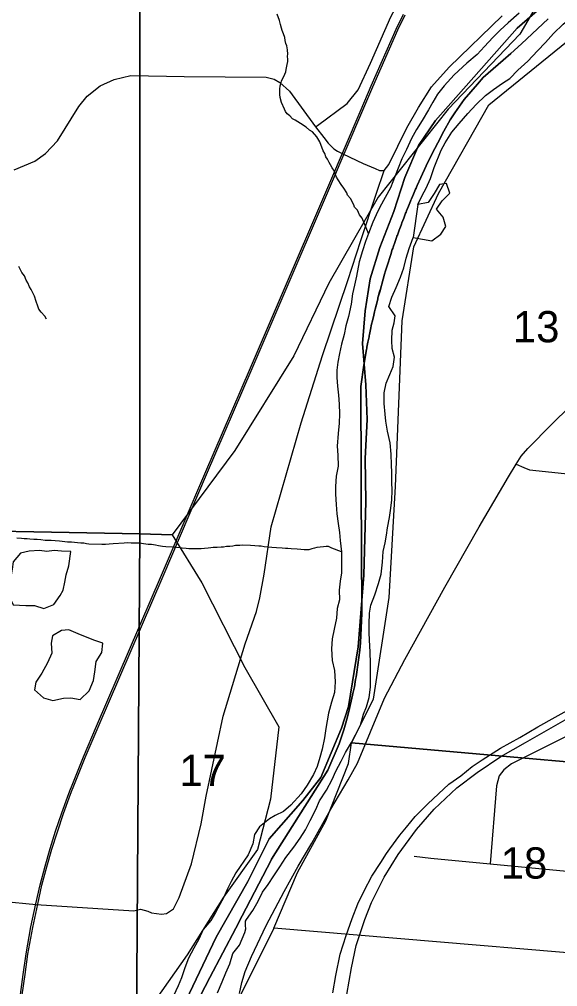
# Model space of a CAD drawing. Extents: x 0 to 34, y 0 to 22.
# Drawn here: x 3.85 to 4.57, y 14.854 to 16.149 of the extents above; entities that cross this region are included whole.
import ezdxf

# ---------------------------------------------------------------- set-up
doc = ezdxf.new("R2010")
doc.units = 0
for name, color, linetype in [('Default', 7, 'Continuous'), ('GM_X_City_Street', 7, 'Continuous'), ('GM_X_Interstate_Route', 7, 'Continuous'), ('GM_X_Major_River', 7, 'Continuous'), ('GM_X_Minor_Lake', 7, 'Continuous'), ('GM_X_Minor_River', 7, 'Continuous'), ('GM_X_Rail_Line', 7, 'Continuous'), ('GM_X_Section', 7, 'Continuous'), ('GM_X_Section_Text', 7, 'Continuous'), ('GM_X_State_Route', 7, 'Continuous'), ('GM_X_Township_Road', 7, 'Continuous'), ('SC_Shading3', 7, 'Continuous')]:
    doc.layers.add(name, color=color, linetype=linetype)

msp = doc.modelspace()

# ---------------------------------------------------------------- linework, layer by layer
at = {"layer": 'Default'}
msp.add_lwpolyline([(3.9705, 14.1), (4.7349, 14.1), (4.7957, 14.8813), (4.1906, 14.9321), (4.0525, 14.6548), (3.9958, 14.4577), (3.9463, 14.3814), (3.9481, 14.3196)], close=True, dxfattribs=at)
at = {"layer": 'GM_X_City_Street'}
for points in [[(4.2465, 16.0051), (4.249, 16.0069), (4.2886, 16.0363), (4.3032, 16.0547), (4.3197, 16.0901), (4.3471, 16.1524), (4.3736, 16.2015), (4.3929, 16.2355), (4.4288, 16.2927), (4.511, 16.4027), (4.5218, 16.4197), (4.5289, 16.4358), (4.5336, 16.4532), (4.5369, 16.4661)], [(4.5149, 15.5535), (4.5216, 15.5642), (4.5305, 15.5745), (4.5624, 15.6068), (4.7794, 15.82), (4.87, 15.9094), (4.8959, 15.9365), (4.9216, 15.9589), (4.9372, 15.9717), (4.9543, 15.9837), (5.0154, 16.0193), (5.0715, 16.0516), (5.1047, 16.0699), (5.1468, 16.091), (5.1632, 16.1008), (5.1685, 16.1061), (5.1775, 16.1154), (5.1852, 16.1256), (5.1933, 16.1399), (5.2233, 16.1956), (5.23, 16.2068), (5.2368, 16.2142), (5.2425, 16.2183)], [(4.0468, 14.9519), (4.0562, 14.9583), (4.0638, 14.9733), (4.0804, 15.0185), (4.0934, 15.0718), (4.0998, 15.1089), (4.1229, 15.216), (4.152, 15.3128), (4.1673, 15.3563), (4.1718, 15.3744), (4.1774, 15.4062), (4.1868, 15.4697), (4.2269, 15.6089), (4.2558, 15.6988), (4.2897, 15.7992), (4.3069, 15.853), (4.328, 15.9162), (4.3382, 15.9467), (4.3445, 15.9547), (4.3686, 16.0037), (4.3841, 16.0311), (4.4017, 16.0587), (4.4251, 16.0847), (4.4959, 16.1536)], [(3.8433, 15.9474), (3.8706, 15.9593), (3.8851, 15.9695), (3.9013, 15.9863), (3.9297, 16.0321), (3.9408, 16.0459), (3.9582, 16.0599), (3.9771, 16.0684), (3.9991, 16.0736), (4.0704, 16.0722), (4.1804, 16.0717), (4.1908, 16.0689), (4.1984, 16.0646), (4.2114, 16.0528), (4.2465, 16.0051)], [(4.2465, 16.0051), (4.2575, 15.9906), (4.2634, 15.9833), (4.2669, 15.9794), (4.271, 15.9756), (4.2758, 15.9726), (4.2827, 15.9688), (4.3101, 15.9561), (4.326, 15.9493), (4.3319, 15.9467), (4.3382, 15.9467)], [(4.1444, 14.8447), (4.1476, 14.8597), (4.1521, 14.8745), (4.1606, 14.8942), (4.1805, 14.9357), (4.2043, 14.9815), (4.2229, 15.0151), (4.2416, 15.0463), (4.2668, 15.0918), (4.2902, 15.131), (4.3023, 15.1533), (4.3198, 15.1951), (4.3386, 15.24), (4.3658, 15.2918), (4.4194, 15.389), (4.4653, 15.4696), (4.5044, 15.5366), (4.5149, 15.5535)], [(4.5149, 15.5535), (4.525, 15.5488), (4.5328, 15.5458), (4.6135, 15.5372), (4.839, 15.5157), (4.85, 15.5147)], [(4.7473, 15.1764), (4.6964, 15.1876), (4.612, 15.1957), (4.6004, 15.1961), (4.5936, 15.195), (4.5869, 15.1914), (4.5085, 15.1522), (4.4981, 15.1441), (4.4919, 15.1361), (4.4886, 15.1229), (4.4801, 15.0184)], [(4.3785, 15.0286), (4.4007, 15.026), (4.4801, 15.0184), (4.6944, 14.9979), (4.7286, 14.9924), (4.8064, 14.9848)], [(3.78, 14.9731), (3.8726, 14.9642), (4.0031, 14.9555), (4.0122, 14.9578), (4.0218, 14.9551), (4.0268, 14.9528), (4.0404, 14.951), (4.0468, 14.9519)]]:
    msp.add_lwpolyline(points, dxfattribs=at)
at = {"layer": 'GM_X_Interstate_Route'}
for points in [[(4.3958, 15.0979), (4.3965, 15.0986), (4.411, 15.1122), (4.4246, 15.1249), (4.4406, 15.1364), (4.4557, 15.1489), (4.4695, 15.1575), (4.4939, 15.1734), (4.5199, 15.1877), (4.544, 15.2017), (4.5943, 15.2301), (4.6364, 15.2539), (4.7317, 15.3079), (4.7824, 15.3368), (4.7921, 15.343)], [(4.3383, 15.0004), (4.3568, 15.0308), (4.3814, 15.0645), (4.4051, 15.0915), (4.4356, 15.12), (4.4626, 15.1408), (4.4941, 15.1619), (4.5273, 15.181), (4.5992, 15.222), (4.6413, 15.2458), (4.7367, 15.2999), (4.7823, 15.3258)], [(4.2695, 14.8457), (4.2734, 14.8691), (4.2795, 14.8977), (4.2873, 14.9227), (4.2953, 14.9451), (4.303, 14.9647), (4.3113, 14.9821), (4.3218, 15.0018), (4.3335, 15.0201), (4.3414, 15.0322), (4.3457, 15.0387), (4.3591, 15.057), (4.3679, 15.0673), (4.3797, 15.0816), (4.3958, 15.0979)], [(4.2876, 14.8397), (4.288, 14.8437), (4.2943, 14.8792), (4.3009, 14.909), (4.3123, 14.9437), (4.3213, 14.9665), (4.3362, 14.997), (4.3383, 15.0004)]]:
    msp.add_lwpolyline(points, dxfattribs=at)
at = {"layer": 'GM_X_Major_River'}
msp.add_line((4.3831, 15.9009), (4.3769, 15.8569), dxfattribs=at)
for points in [[(4.5186, 16.1571), (4.5039, 16.1441), (4.4935, 16.1344), (4.4834, 16.1248), (4.4726, 16.1124), (4.4625, 16.102), (4.449, 16.0901), (4.432, 16.0748), (4.4184, 16.0599), (4.4095, 16.0486), (4.4032, 16.0381), (4.3973, 16.0279), (4.3891, 16.0137), (4.3816, 16.0016), (4.3749, 15.9892), (4.3682, 15.9745), (4.3619, 15.9621), (4.3571, 15.9496), (4.3531, 15.9395), (4.3467, 15.9236), (4.3396, 15.9104), (4.3322, 15.8977), (4.3274, 15.8871), (4.3231, 15.8773), (4.3171, 15.8622), (4.3131, 15.8516), (4.3094, 15.8392), (4.3046, 15.8241), (4.3012, 15.8051), (4.2986, 15.793), (4.2958, 15.7816), (4.294, 15.7676), (4.2903, 15.7513), (4.287, 15.7385), (4.2848, 15.7271), (4.2812, 15.7139), (4.2783, 15.7018), (4.2762, 15.69), (4.2748, 15.6794), (4.275, 15.6695), (4.2759, 15.6577), (4.2772, 15.6459), (4.2781, 15.6337), (4.2782, 15.6208), (4.278, 15.6082), (4.2766, 15.5946), (4.2755, 15.5775), (4.2764, 15.5653)], [(4.3831, 15.9009), (4.389, 15.9129), (4.3945, 15.9231), (4.4001, 15.9359), (4.4049, 15.9506), (4.4145, 15.974), (4.42, 15.9838), (4.4286, 15.9981), (4.4387, 16.0097), (4.4503, 16.0231), (4.4612, 16.0351), (4.4739, 16.047), (4.4843, 16.0548), (4.4966, 16.0633), (4.5063, 16.0699), (4.5171, 16.0811), (4.5302, 16.093), (4.5434, 16.1069), (4.5542, 16.1181), (4.5647, 16.13), (4.5779, 16.1427), (4.5929, 16.1553)], [(4.3769, 15.8569), (4.4019, 15.8526), (4.4138, 15.8615), (4.4208, 15.8716), (4.4169, 15.8842), (4.408, 15.8947), (4.4158, 15.9059), (4.4262, 15.9164), (4.4216, 15.9294), (4.4121, 15.928), (4.405, 15.9156), (4.3972, 15.9036), (4.3831, 15.9009)], [(4.1152, 14.8456), (4.1215, 14.8606), (4.1263, 14.8723), (4.1315, 14.8844), (4.1359, 14.8984), (4.1445, 14.9096), (4.1517, 14.9266), (4.1529, 14.9315), (4.1526, 14.9357), (4.1527, 14.9414), (4.1527, 14.9418), (4.1539, 14.9441), (4.1625, 14.9561), (4.1695, 14.9685), (4.1755, 14.9805), (4.1829, 14.9907), (4.1907, 15.0023), (4.1985, 15.0143), (4.2067, 15.0267), (4.2172, 15.0406), (4.2258, 15.0526), (4.2329, 15.0638), (4.2392, 15.0766), (4.2467, 15.0913), (4.2518, 15.1026), (4.2608, 15.1169), (4.2687, 15.1312), (4.2735, 15.1425), (4.2805, 15.1557), (4.2865, 15.1674), (4.2943, 15.1809), (4.2998, 15.1911), (4.3065, 15.2042), (4.3106, 15.2186), (4.3146, 15.2284), (4.3183, 15.2409), (4.32, 15.2549), (4.32, 15.2713), (4.3199, 15.2865), (4.3194, 15.3021), (4.3186, 15.3177), (4.318, 15.328), (4.3179, 15.3394), (4.3186, 15.3538), (4.3203, 15.3648), (4.3259, 15.3784), (4.3307, 15.3939), (4.334, 15.406), (4.3358, 15.4223), (4.3369, 15.4364), (4.3394, 15.4481), (4.3411, 15.4583), (4.3428, 15.4682), (4.3453, 15.4822), (4.3471, 15.4947), (4.3484, 15.5057), (4.3491, 15.5183), (4.3485, 15.5293), (4.3484, 15.5422), (4.3482, 15.5525), (4.3477, 15.567), (4.3461, 15.5818), (4.3427, 15.5978), (4.3402, 15.6108), (4.3397, 15.6203), (4.3381, 15.6348), (4.3383, 15.6489), (4.3409, 15.6618), (4.3456, 15.6735), (4.35, 15.6844), (4.3518, 15.6969), (4.349, 15.7084), (4.3484, 15.719), (4.3491, 15.7327), (4.3515, 15.7425), (4.3529, 15.752), (4.3444, 15.7644), (4.3484, 15.7772), (4.3544, 15.79), (4.3599, 15.804), (4.3644, 15.8161), (4.3676, 15.8293), (4.3717, 15.8421), (4.3769, 15.8569)], [(4.2764, 15.5653), (4.2765, 15.5508), (4.2739, 15.5376), (4.2729, 15.5235), (4.2731, 15.5133), (4.274, 15.4996), (4.2749, 15.487), (4.2765, 15.474), (4.2785, 15.4618), (4.2795, 15.4512), (4.2811, 15.4359), (4.2812, 15.4215), (4.2809, 15.4082), (4.2792, 15.3968), (4.2778, 15.385), (4.2783, 15.3717), (4.2754, 15.3604), (4.2744, 15.3471), (4.2711, 15.3327), (4.2686, 15.3198), (4.2679, 15.3061), (4.2688, 15.2905), (4.2715, 15.2772), (4.2728, 15.2619), (4.2717, 15.2479), (4.2677, 15.2347), (4.2636, 15.2203), (4.2602, 15.1994), (4.2584, 15.1873), (4.2551, 15.1718), (4.2522, 15.1608), (4.2485, 15.1487), (4.2438, 15.1378), (4.2352, 15.1239), (4.2273, 15.1122), (4.2134, 15.0969), (4.2037, 15.0887), (4.1923, 15.0831)], [(4.1923, 15.0831), (4.1846, 15.0788), (4.1715, 15.0681), (4.1648, 15.0579), (4.1623, 15.0451), (4.1563, 15.0303), (4.1399, 15.0063), (4.1336, 14.9947), (4.1281, 14.9841), (4.1237, 14.9739), (4.1182, 14.9638), (4.1123, 14.9532), (4.1061, 14.9427), (4.096, 14.9304), (4.09, 14.9175), (4.0837, 14.9055), (4.0762, 14.8923), (4.0714, 14.8791), (4.067, 14.8659), (4.0626, 14.8549), (4.0563, 14.8418)]]:
    msp.add_lwpolyline(points, dxfattribs=at)
at = {"layer": 'GM_X_Minor_Lake'}
for points in [[(3.9188, 15.4365), (3.9063, 15.4371), (3.8964, 15.4377), (3.8869, 15.4367), (3.8771, 15.4377), (3.863, 15.4368), (3.8516, 15.4344), (3.8419, 15.4228), (3.8402, 15.4129), (3.8388, 15.4027), (3.8375, 15.3909), (3.8364, 15.3769), (3.8419, 15.365), (3.8586, 15.3643), (3.8703, 15.3641), (3.8828, 15.3604), (3.8961, 15.3655), (3.9047, 15.3778)], [(3.9047, 15.3778), (3.9087, 15.385), (3.9108, 15.3956), (3.9129, 15.4054), (3.9161, 15.4172), (3.9188, 15.4365)], [(3.9288, 15.3264), (3.9164, 15.3316), (3.9065, 15.331), (3.8942, 15.3237), (3.8925, 15.3138), (3.8934, 15.3005), (3.8878, 15.2877), (3.8803, 15.2737), (3.8721, 15.2614), (3.8704, 15.2515), (3.8823, 15.2406), (3.8948, 15.2373), (3.9093, 15.2401), (3.9188, 15.2407), (3.9312, 15.2382), (3.9436, 15.2501), (3.9492, 15.2637)], [(3.9492, 15.2637), (3.9509, 15.2754), (3.9527, 15.2894), (3.9605, 15.3015), (3.9619, 15.314), (3.9495, 15.3177), (3.9288, 15.3264)]]:
    msp.add_lwpolyline(points, dxfattribs=at)
at = {"layer": 'GM_X_Minor_River'}
for points in [[(4.3171, 15.8622), (4.3086, 15.8826), (4.3053, 15.8873), (4.3024, 15.8934), (4.2987, 15.8977), (4.2977, 15.9008), (4.2933, 15.9089), (4.2892, 15.9135), (4.2882, 15.9166), (4.2841, 15.9228), (4.2808, 15.9278), (4.2768, 15.934), (4.2746, 15.9378), (4.2724, 15.9421), (4.2718, 15.9459), (4.2685, 15.9502), (4.2663, 15.954), (4.2645, 15.9571), (4.2623, 15.9617), (4.2601, 15.9648), (4.2587, 15.9694), (4.2565, 15.9729), (4.2522, 15.9851), (4.2482, 15.9917), (4.2423, 15.9983), (4.2381, 16.0007), (4.2337, 16.0046), (4.2262, 16.0094), (4.2191, 16.0141), (4.2153, 16.0157), (4.212, 16.0196), (4.2083, 16.0223), (4.206, 16.0254), (4.2046, 16.0285), (4.2006, 16.0374), (4.1989, 16.0442), (4.1986, 16.0484), (4.1987, 16.0515), (4.1984, 16.0553), (4.1989, 16.0598), (4.1997, 16.0628), (4.201, 16.0662), (4.2022, 16.0692), (4.2038, 16.0726), (4.2054, 16.0756), (4.2066, 16.0786), (4.207, 16.0817), (4.2084, 16.0885), (4.2092, 16.0923), (4.2093, 16.0953), (4.209, 16.0995), (4.2091, 16.1025), (4.2088, 16.1082), (4.2078, 16.1136), (4.2068, 16.1166), (4.2057, 16.1208), (4.2051, 16.1247), (4.2037, 16.1296), (4.2019, 16.1342), (4.2008, 16.1373), (4.1994, 16.1419), (4.198, 16.1473), (4.1948, 16.1557)], [(3.8862, 15.7475), (3.884, 15.7517), (3.8792, 15.7568), (3.8763, 15.7611), (3.8749, 15.7649), (3.8724, 15.771), (3.8703, 15.7783), (3.8684, 15.7818), (3.8659, 15.7875), (3.8637, 15.791), (3.8616, 15.7964), (3.859, 15.7999), (3.8568, 15.8056), (3.8535, 15.8099), (3.8495, 15.818)], [(4.2811, 15.4359), (4.2681, 15.4408), (4.2636, 15.4432), (4.2606, 15.4433), (4.2571, 15.443), (4.2525, 15.4423), (4.2483, 15.4417), (4.2449, 15.441), (4.2415, 15.44), (4.2373, 15.4389), (4.2342, 15.4386), (4.2312, 15.4387), (4.2266, 15.4392), (4.2217, 15.4397), (4.2137, 15.4403), (4.2091, 15.4404), (4.2061, 15.4405), (4.2019, 15.4409), (4.194, 15.4415), (4.1879, 15.442), (4.1822, 15.4422), (4.1776, 15.4427), (4.1735, 15.4435), (4.1704, 15.4436), (4.1651, 15.4441), (4.1594, 15.4446), (4.1484, 15.4449), (4.145, 15.4446), (4.1393, 15.4444), (4.1355, 15.4437), (4.1316, 15.4434), (4.1274, 15.4432), (4.1233, 15.4425), (4.1202, 15.4422), (4.1149, 15.442), (4.1092, 15.4417), (4.1061, 15.4414), (4.1027, 15.4411), (4.0977, 15.4405), (4.0932, 15.4402), (4.089, 15.4403), (4.084, 15.4401), (4.0802, 15.4401), (4.0768, 15.4402), (4.0734, 15.4407), (4.0681, 15.4408), (4.0647, 15.4413), (4.0601, 15.4418), (4.0548, 15.4423), (4.0461, 15.4429), (4.0415, 15.4434), (4.0362, 15.4443), (4.0324, 15.4448), (4.0267, 15.4457), (4.0222, 15.4461), (4.0161, 15.4467), (4.0108, 15.4476), (4.0051, 15.4477), (3.9998, 15.4478), (3.9948, 15.448), (3.9903, 15.4477), (3.9754, 15.4469), (3.9701, 15.4463), (3.9651, 15.446), (3.9606, 15.4458), (3.9431, 15.4462), (3.94, 15.4467), (3.9363, 15.4475), (3.9321, 15.4476), (3.9279, 15.4481), (3.92, 15.4491), (3.9143, 15.4492), (3.9074, 15.4501), (3.9036, 15.4502), (3.8979, 15.4507), (3.8926, 15.4512), (3.8846, 15.4514), (3.8786, 15.452), (3.874, 15.4525), (3.8695, 15.4526), (3.8641, 15.4531), (3.8607, 15.4536), (3.8566, 15.4537), (3.8531, 15.4541), (3.8467, 15.4543)]]:
    msp.add_lwpolyline(points, dxfattribs=at)
at = {"layer": 'GM_X_Rail_Line'}
for points in [[(3.8516, 14.8433), (3.8552, 14.8705), (3.859, 14.8978), (3.8656, 14.9339), (3.8722, 14.965), (3.8779, 14.9904), (3.8845, 15.0151), (3.8913, 15.0389), (3.8986, 15.0622), (3.907, 15.0867), (3.9145, 15.1077), (3.9175, 15.1162), (3.9206, 15.1239), (3.936, 15.1617), (3.9532, 15.2026), (4.0402, 15.4047), (4.0982, 15.5407), (4.1593, 15.6826), (4.1982, 15.7729), (4.2643, 15.927), (4.3073, 16.0284), (4.3208, 16.0598), (4.3543, 16.1358), (4.3639, 16.1559)], [(3.854, 14.843), (3.8577, 14.8702), (3.8615, 14.8974), (3.868, 14.9334), (3.8746, 14.9645), (3.8803, 14.9898), (3.8869, 15.0144), (3.8936, 15.0382), (3.9009, 15.0614), (3.9093, 15.0859), (3.9169, 15.1069), (3.9198, 15.1153), (3.9229, 15.123), (3.9383, 15.1608), (3.9555, 15.2016), (4.0425, 15.4037), (4.1004, 15.5397), (4.1616, 15.6816), (4.2005, 15.772), (4.2665, 15.926), (4.3096, 16.0275), (4.3231, 16.0588), (4.3565, 16.1348), (4.3662, 16.1548)]]:
    msp.add_lwpolyline(points, dxfattribs=at)
at = {"layer": 'GM_X_Section'}
for points in [[(3.0135, 16.4807), (4.0113, 16.4768), (4.0112, 15.46), (3.0168, 15.4789)], [(4.0113, 16.4768), (5.016, 16.4735), (5.0144, 16.4489), (4.9559, 16.4588), (4.9027, 16.4533), (4.8303, 16.4274), (4.767, 16.3854), (4.6663, 16.3267), (4.586, 16.2434), (4.5198, 16.1291), (4.4237, 16.0287), (4.3302, 15.9111), (4.264, 15.7957), (4.2171, 15.6985), (4.1382, 15.5716), (4.0543, 15.4588), (4.0112, 15.46)], [(4.6046, 16.1438), (4.9109, 16.1221), (4.8205, 15.1342), (4.2945, 15.1804), (4.324, 15.239), (4.3447, 15.3749), (4.3532, 15.5236), (4.3623, 15.7454), (4.3778, 15.8443), (4.4109, 15.9156), (4.4783, 16.0344), (4.5821, 16.1188)], [(3.0168, 15.4789), (4.0112, 15.46), (4.0068, 14.8003), (3.9922, 14.7706), (3.9618, 14.7034), (3.9313, 14.6142), (3.9035, 14.5261), (3.8947, 14.4604), (3.0051, 14.4664), (3.0163, 15.4353)], [(4.0112, 15.46), (4.0543, 15.4588), (4.0944, 15.3944), (4.1517, 15.2812), (4.1972, 15.202), (4.1863, 15.1048), (4.1688, 15.0374), (4.1233, 14.9738), (4.0748, 14.8967), (4.0068, 14.8003)], [(4.2945, 15.1804), (4.8205, 15.1342), (4.7957, 14.8813), (4.1906, 14.9321), (4.222, 15.0068), (4.26, 15.0762), (4.2906, 15.1529)]]:
    msp.add_lwpolyline(points, close=True, dxfattribs=at)
at = {"layer": 'GM_X_State_Route'}
msp.add_lwpolyline([(4.0435, 14.7476), (4.1051, 14.8662), (4.1395, 14.9324), (4.148, 14.9487), (4.1868, 15.0235), (4.1876, 15.0247), (4.2626, 15.1439), (4.2781, 15.179), (4.2812, 15.1884), (4.2841, 15.1979), (4.2869, 15.2074), (4.2895, 15.2169), (4.2919, 15.2265), (4.2942, 15.2361), (4.296, 15.2441), (4.2964, 15.2463), (4.2983, 15.2555), (4.2994, 15.262), (4.3, 15.2652), (4.3006, 15.2686), (4.3016, 15.275), (4.303, 15.2848), (4.3043, 15.2946), (4.3054, 15.3044), (4.3063, 15.3143), (4.307, 15.3241), (4.3076, 15.334), (4.308, 15.3439), (4.3082, 15.3538), (4.3082, 15.364), (4.3082, 15.378), (4.308, 15.4196), (4.3071, 15.6575), (4.3109, 15.686), (4.3146, 15.7068), (4.3149, 15.7088), (4.3152, 15.7101), (4.3165, 15.7169), (4.3179, 15.7238), (4.3182, 15.7254), (4.3185, 15.7271), (4.32, 15.7339), (4.3214, 15.7407), (4.3218, 15.7423), (4.3222, 15.744), (4.3238, 15.7508), (4.3253, 15.7576), (4.3257, 15.7592), (4.3261, 15.7608), (4.3278, 15.7676), (4.3295, 15.7744), (4.3299, 15.776), (4.3303, 15.7776), (4.3321, 15.7842), (4.3335, 15.7892), (4.334, 15.7911), (4.3344, 15.7926), (4.3349, 15.7942), (4.3368, 15.801), (4.3387, 15.8077), (4.3392, 15.8093), (4.3397, 15.8109), (4.3418, 15.8175), (4.3438, 15.8242), (4.3443, 15.8258), (4.3448, 15.8274), (4.347, 15.834), (4.3491, 15.8407), (4.3497, 15.8422), (4.3502, 15.8438), (4.3525, 15.8504), (4.3548, 15.857), (4.3553, 15.8586), (4.3559, 15.8601), (4.3583, 15.8667), (4.3607, 15.8733), (4.3613, 15.8748), (4.3618, 15.8764), (4.3644, 15.8829), (4.3669, 15.8894), (4.3675, 15.8909), (4.3681, 15.8925), (4.3707, 15.899), (4.3733, 15.9054), (4.374, 15.907), (4.3746, 15.9085), (4.3774, 15.9149), (4.3801, 15.9214), (4.3808, 15.9229), (4.3814, 15.9244), (4.3823, 15.9264), (4.3871, 15.9372), (4.3944, 15.9528), (4.402, 15.9684), (4.4098, 15.9838), (4.418, 15.9991), (4.4263, 16.0142), (4.4329, 16.0236), (4.4454, 16.0417), (4.463, 16.0622), (4.4708, 16.0713), (4.4973, 16.0941), (4.5078, 16.1031), (4.5218, 16.1162), (4.5574, 16.1495)], dxfattribs=at)
at = {"layer": 'GM_X_Township_Road'}
for points in [[(4.0327, 14.7508), (4.1134, 14.9203), (4.1556, 14.9946), (4.1842, 15.0518), (4.2295, 15.103), (4.2535, 15.1338), (4.281, 15.1999), (4.2904, 15.229), (4.3033, 15.3088), (4.311, 15.4048), (4.3136, 15.5034), (4.3127, 15.5609), (4.3153, 15.6132), (4.3136, 15.6595), (4.3093, 15.7152), (4.3127, 15.7588), (4.3196, 15.8017), (4.3324, 15.8437), (4.3513, 15.8917), (4.3659, 15.9372), (4.3839, 15.98), (4.407, 16.0135), (4.516, 16.137), (4.5563, 16.1721)], [(4.5563, 16.1721), (4.516, 16.137), (4.407, 16.0135), (4.3839, 15.98), (4.3659, 15.9372), (4.3513, 15.8917), (4.3324, 15.8437), (4.3196, 15.8017), (4.3127, 15.7588), (4.3093, 15.7152), (4.3136, 15.6595), (4.3153, 15.6132), (4.3127, 15.5609), (4.3136, 15.5034), (4.311, 15.4048), (4.3033, 15.3088), (4.2904, 15.229), (4.281, 15.1999), (4.2535, 15.1338), (4.2295, 15.103), (4.1842, 15.0518), (4.1556, 14.9946), (4.1134, 14.9203), (4.0327, 14.7508)]]:
    msp.add_lwpolyline(points, dxfattribs=at)
at = {"layer": 'SC_Shading3'}
msp.add_lwpolyline([(4.5574, 16.1495), (4.5218, 16.1162), (4.5078, 16.1031), (4.4973, 16.0941), (4.4708, 16.0713), (4.463, 16.0622), (4.4454, 16.0417), (4.4329, 16.0236), (4.4263, 16.0142), (4.418, 15.9991), (4.4098, 15.9838), (4.402, 15.9684), (4.3944, 15.9528), (4.3871, 15.9372), (4.3823, 15.9264), (4.3814, 15.9244), (4.3808, 15.9229), (4.3801, 15.9214), (4.3774, 15.9149), (4.3746, 15.9085), (4.374, 15.907), (4.3733, 15.9054), (4.3707, 15.899), (4.3681, 15.8925), (4.3675, 15.8909), (4.3669, 15.8894), (4.3644, 15.8829), (4.3618, 15.8764), (4.3613, 15.8748), (4.3607, 15.8733), (4.3583, 15.8667), (4.3559, 15.8601), (4.3553, 15.8586), (4.3548, 15.857), (4.3525, 15.8504), (4.3502, 15.8438), (4.3497, 15.8422), (4.3491, 15.8407), (4.347, 15.834), (4.3448, 15.8274), (4.3443, 15.8258), (4.3438, 15.8242), (4.3418, 15.8175), (4.3397, 15.8109), (4.3392, 15.8093), (4.3387, 15.8077), (4.3368, 15.801), (4.3349, 15.7942), (4.3344, 15.7926), (4.334, 15.7911), (4.3335, 15.7892), (4.3322, 15.7843), (4.3303, 15.7776), (4.3299, 15.776), (4.3295, 15.7744), (4.3278, 15.7676), (4.3278, 15.7674), (4.3261, 15.7608), (4.3257, 15.7592), (4.3253, 15.7576), (4.3238, 15.7508), (4.3222, 15.744), (4.3218, 15.7423), (4.3214, 15.7407), (4.32, 15.7339), (4.3185, 15.7271), (4.3182, 15.7254), (4.3179, 15.7238), (4.3165, 15.7169), (4.3152, 15.7101), (4.3149, 15.7088), (4.3146, 15.7068), (4.3109, 15.686), (4.3071, 15.6575), (4.308, 15.4196), (4.3082, 15.378), (4.3082, 15.364), (4.3082, 15.3538), (4.308, 15.3439), (4.3076, 15.334), (4.307, 15.3241), (4.3063, 15.3143), (4.3054, 15.3044), (4.3043, 15.2946), (4.303, 15.2848), (4.3016, 15.275), (4.3006, 15.2686), (4.3, 15.2652), (4.2994, 15.262), (4.2983, 15.2555), (4.2964, 15.2463), (4.2963, 15.2458), (4.296, 15.2441), (4.2942, 15.2361), (4.2919, 15.2265), (4.2895, 15.2169), (4.2869, 15.2074), (4.2841, 15.1979), (4.2812, 15.1884), (4.2781, 15.179), (4.2626, 15.1439), (4.1876, 15.0247), (4.1868, 15.0235), (4.148, 14.9487), (4.1395, 14.9324), (4.1051, 14.8662), (4.0435, 14.7476)], dxfattribs=at)

# ---------------------------------------------------------------- texts
at = {"layer": 'GM_X_Section_Text'}
for s, p in [('13', (4.5104, 15.7166)), ('17', (4.0641, 15.1225)), ('18', (4.4941, 14.9987))]:
    msp.add_text(s, height=0.04186, rotation=0, dxfattribs=at).set_placement(p)

doc.saveas('drawing.dxf')
